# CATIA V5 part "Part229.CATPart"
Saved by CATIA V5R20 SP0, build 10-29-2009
Part number: DFA 168700-3
Revision: ANY
Definition: UNKNOWN
Nomenclature: DFA 168700-3
Source: Unknown
Bounding box of the stored display mesh (mm): x -3 to 3, y 0 to 4.95, z -3.464 to 3.464
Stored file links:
  C:\Users\Utente\Desktop\IO LAVORO\3D X SITO CF\CUMSA\3D files FA\FA 200712-21\Part229.CATPart
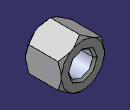
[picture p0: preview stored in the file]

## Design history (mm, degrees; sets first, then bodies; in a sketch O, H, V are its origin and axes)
Body1 "Cortar-Extruir3" (main body)
  Solid1: solid without history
